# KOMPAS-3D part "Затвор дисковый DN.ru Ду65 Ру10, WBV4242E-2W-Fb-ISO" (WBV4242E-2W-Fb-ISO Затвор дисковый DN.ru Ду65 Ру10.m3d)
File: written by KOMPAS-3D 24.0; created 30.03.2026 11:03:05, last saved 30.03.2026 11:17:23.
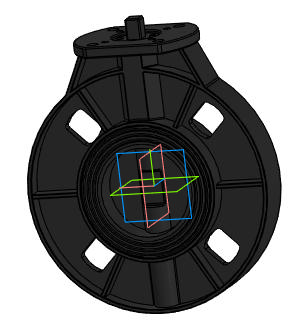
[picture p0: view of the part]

Document properties: Автор: R2D2; Полное имя файла: WBV4242E-2W-Fb-ISO Затвор дисковый DN.ru Ду65 Ру10.cdw

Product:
- Part/product: Затвор дисковый DN.ru Ду65 Ру10  | designation WBV4242E-2W-Fb-ISO
    Масса: 1
    Раздел спецификации: Прочие изделия
    Форматы листов документа: A2
    Примечание: D050-81205

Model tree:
1. Операция без истории:1

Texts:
  WBV4242E-2W-Fb-ISO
